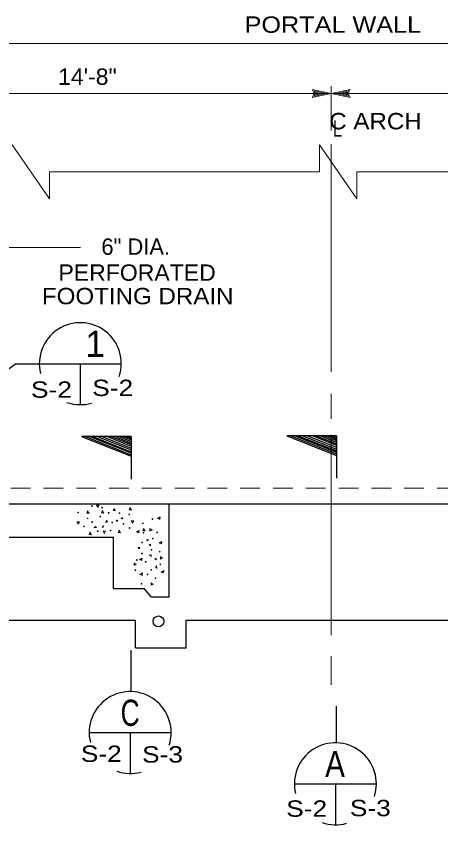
# Model space of a CAD drawing. Extents: x -22.3 to 19.7, y -11.8 to 18.2.
# Drawn here: x -7.13 to -3.89, y 0.19 to 6.36 of the extents above; entities that cross this region are included whole.
import ezdxf
from ezdxf.enums import TextEntityAlignment as Align

# ---------------------------------------------------------------- set-up
doc = ezdxf.new("R2010")
doc.units = 0
doc.header["$LTSCALE"] = 0.05
doc.linetypes.add('MEDIUM_DASHED', pattern=[4.5, 3, -1.5])
doc.layers.add('1', color=7, linetype='Continuous', lineweight=13)
doc.layers.add('2', color=7, linetype='Continuous', lineweight=13)

msp = doc.modelspace()

# ---------------------------------------------------------------- linework, layer by layer
at = {"layer": '1'}
for p, q in [((-8.42042, 6.14831), (-1.02142, 6.14831)), ((-4.72742, 5.76631), (-4.87142, 5.79731)), ((-4.72742, 5.48331), (-4.72742, 5.82331)), ((-4.72742, 5.76631), (-4.58342, 5.79731)), ((-4.72742, 5.76631), (-4.87142, 5.73531)), ((-4.76442, 5.76631), (-4.85842, 5.78631)), ((-4.84942, 5.76631), (-4.85842, 5.78631)), ((-4.76442, 5.76631), (-4.85842, 5.74631)), ((-4.85842, 5.74631), (-4.84942, 5.76631)), ((-4.80042, 5.76631), (-4.84542, 5.77531)), ((-4.84142, 5.76631), (-4.84542, 5.77531)), ((-4.80042, 5.76631), (-4.84542, 5.75631)), ((-4.84542, 5.75631), (-4.84142, 5.76631)), ((-4.72742, 5.76631), (-4.58342, 5.73531)), ((-4.69042, 5.76631), (-4.59642, 5.78631)), ((-4.69042, 5.76631), (-4.59642, 5.74631)), ((-4.65442, 5.76631), (-4.60942, 5.77631)), ((-4.65442, 5.76631), (-4.60942, 5.75731)), ((-4.60942, 5.77631), (-4.61342, 5.76631)), ((-4.61342, 5.76631), (-4.60942, 5.75731)), ((-4.59642, 5.78631), (-4.60542, 5.76631)), ((-4.60542, 5.76631), (-4.59642, 5.74631)), ((-6.87442, 4.96231), (-7.15942, 5.37531)), ((-4.81642, 5.16931), (-4.81642, 5.37531)), ((-4.53142, 4.96231), (-4.81642, 5.37531)), ((-4.72742, 3.64431), (-4.72742, 5.38031)), ((-6.87442, 4.96231), (-6.87442, 5.16931)), ((-6.87442, 5.16931), (-4.81642, 5.16931)), ((-4.53142, 4.96231), (-4.53142, 5.16931)), ((-4.53142, 5.16931), (-2.63142, 5.16931)), ((-4.72742, 3.28631), (-4.72742, 3.47531)), ((-4.72742, 1.63631), (-4.72742, 3.16331)), ((-4.72742, 1.25731), (-4.72742, 1.47531))]:
    msp.add_line(p, q, dxfattribs=at)
at = {"layer": '1', "linetype": 'MEDIUM_DASHED'}
msp.add_line((-8.42042, 2.75631), (-1.02142, 2.75631), dxfattribs=at)
at = {"layer": '1', "lineweight": 25}
for p, q in [((-8.42042, 2.63731), (-1.02142, 2.63731)), ((-5.96342, 1.92531), (-5.96342, 2.63731)), ((-17.08742, 2.38431), (-6.38842, 2.38431)), ((-6.38842, 1.99231), (-6.38842, 2.38431)), ((-6.38842, 1.99231), (-6.15242, 1.99231)), ((-6.09842, 1.92531), (-6.15242, 1.99231)), ((-5.96342, 1.92531), (-6.09842, 1.92531)), ((-8.41542, 1.75131), (-6.21842, 1.75131)), ((-6.21842, 1.53931), (-6.21842, 1.75131)), ((-5.83442, 1.75131), (-3.59642, 1.75131)), ((-5.83442, 1.53931), (-5.83442, 1.75131)), ((-6.21842, 1.53931), (-5.83442, 1.53931))]:
    msp.add_line(p, q, dxfattribs=at)
at = {"layer": '1'}
for points in [[(-4.87142, 5.73531), (-4.85742, 5.76631), (-4.87142, 5.79731)], [(-4.58342, 5.79731), (-4.59742, 5.76631), (-4.58342, 5.73531)], [(-8.42042, 5.76631), (-4.72742, 5.76631), (-1.02142, 5.76631)], [(-8.60842, 3.12131), (-7.23742, 4.59331), (-6.63942, 4.59331)]]:
    msp.add_lwpolyline(points, dxfattribs=at)
at = {"layer": '1', "lineweight": 25}
msp.add_lwpolyline([(-8.34342, 2.81631), (-7.13542, 3.70631), (-6.95242, 3.70631)], dxfattribs=at)
msp.add_circle((-6.04442, 1.74131), 0.0412, dxfattribs=at)
at = {"layer": '2', "lineweight": 25}
for p, q in [((-6.95242, 3.70631), (-6.32842, 3.70631)), ((-6.64042, 3.70631), (-6.64042, 3.39431)), ((-6.60042, 3.15031), (-6.25242, 3.01231)), ((-6.56742, 3.15031), (-6.25242, 3.02531)), ((-6.54442, 3.15031), (-6.25242, 3.03431)), ((-6.50842, 3.15031), (-6.25242, 3.04831)), ((-6.47442, 3.15031), (-6.25242, 3.06231)), ((-6.43342, 3.15031), (-6.25242, 3.07831)), ((-6.40642, 3.15031), (-6.25242, 3.08931)), ((-6.37442, 3.15031), (-6.25242, 3.10131)), ((-6.34542, 3.15031), (-6.25242, 3.11331)), ((-6.31642, 3.15031), (-6.25242, 3.12431)), ((-6.29642, 3.15031), (-6.25242, 3.13231)), ((-6.26942, 3.15031), (-6.25242, 3.14331)), ((-6.25242, 3.15031), (-6.25242, 2.82631)), ((-5.03542, 3.15731), (-4.68742, 3.01931)), ((-5.00242, 3.15731), (-4.68742, 3.03231)), ((-4.97942, 3.15731), (-4.68742, 3.04131)), ((-4.94342, 3.15731), (-4.68742, 3.05531)), ((-4.90942, 3.15731), (-4.68742, 3.06931)), ((-4.86842, 3.15731), (-4.68742, 3.08531)), ((-4.84142, 3.15731), (-4.68742, 3.09631)), ((-4.80942, 3.15731), (-4.68742, 3.10831)), ((-4.78042, 3.15731), (-4.68742, 3.12031)), ((-4.75142, 3.15731), (-4.68742, 3.13131)), ((-4.73142, 3.15731), (-4.68742, 3.13931)), ((-4.70442, 3.15731), (-4.68742, 3.15031)), ((-4.68742, 3.15731), (-4.68742, 2.83331)), ((-6.25242, 1.20731), (-6.25242, 1.52231)), ((-4.68742, 0.81631), (-4.68742, 1.09531)), ((-6.57242, 0.89331), (-5.94842, 0.89331)), ((-6.26042, 0.89331), (-6.26042, 0.58131)), ((-5.00742, 0.50231), (-4.38342, 0.50231)), ((-4.69542, 0.50231), (-4.69542, 0.19031))]:
    msp.add_line(p, q, dxfattribs=at)
at = {"layer": '2'}
for p, q in [((-6.38942, 2.59031), (-6.37942, 2.59931)), ((-6.19142, 2.29431), (-6.20042, 2.30431))]:
    msp.add_line(p, q, dxfattribs=at)
at = {"layer": '2', "lineweight": 25}
for points in [[(-6.25242, 3.15031), (-6.63142, 3.15031), (-6.25242, 3.00031)], [(-4.68742, 3.15731), (-5.06642, 3.15731), (-4.68742, 3.00731)]]:
    msp.add_lwpolyline(points, dxfattribs=at)
at = {"layer": '2'}
for points in [[(-6.50742, 2.61231), (-6.51642, 2.62831), (-6.49742, 2.62831), (-6.50742, 2.61031)], [(-6.37942, 2.60131), (-6.37542, 2.58731), (-6.38942, 2.58731)], [(-6.25942, 2.61031), (-6.26842, 2.59231), (-6.24942, 2.59031), (-6.26342, 2.61031)], [(-6.58242, 2.58531), (-6.59142, 2.56731), (-6.57242, 2.56631), (-6.58742, 2.58531)], [(-6.47042, 2.58731), (-6.47942, 2.56931), (-6.46142, 2.56731), (-6.47442, 2.58731)], [(-6.33042, 2.52831), (-6.32142, 2.53131), (-6.31742, 2.52231), (-6.33042, 2.52631)], [(-6.05142, 2.52831), (-6.03342, 2.51931), (-6.03242, 2.53731), (-6.05142, 2.52331)], [(-6.65842, 2.48531), (-6.66742, 2.50031), (-6.64742, 2.50031), (-6.65842, 2.48231)], [(-6.36642, 2.50431), (-6.36042, 2.51331), (-6.35342, 2.50431), (-6.36442, 2.50431)], [(-6.24442, 2.49331), (-6.25342, 2.50831), (-6.23342, 2.50831), (-6.24442, 2.48931)], [(-6.56442, 2.42231), (-6.57342, 2.40431), (-6.55442, 2.40231), (-6.56942, 2.42231)], [(-6.53442, 2.45831), (-6.52542, 2.46431), (-6.51642, 2.45831), (-6.53842, 2.45531)], [(-6.45842, 2.41331), (-6.46742, 2.42831), (-6.44742, 2.42831), (-6.45842, 2.40931)], [(-6.34242, 2.43731), (-6.35142, 2.41931), (-6.33342, 2.41731), (-6.34642, 2.43731)], [(-6.21142, 2.42431), (-6.19342, 2.41531), (-6.19142, 2.43431), (-6.21142, 2.42031)], [(-6.15542, 2.45031), (-6.16442, 2.43231), (-6.14642, 2.43131), (-6.16042, 2.45031)], [(-6.09442, 2.43931), (-6.10942, 2.43031), (-6.10942, 2.45031), (-6.09042, 2.43931)], [(-6.12942, 2.35331), (-6.13242, 2.36231), (-6.12342, 2.36631), (-6.12742, 2.35331)], [(-6.03842, 2.34131), (-6.02042, 2.33231), (-6.01842, 2.35031), (-6.03842, 2.33731)], [(-6.20242, 2.30431), (-6.18842, 2.30831), (-6.18842, 2.29431)], [(-6.10542, 2.31731), (-6.11442, 2.32331), (-6.10542, 2.33031), (-6.10542, 2.31931)], [(-6.18842, 2.21331), (-6.17042, 2.20431), (-6.16842, 2.22231), (-6.18842, 2.20931)], [(-6.01442, 2.22531), (-6.02942, 2.21631), (-6.02942, 2.23631), (-6.01042, 2.22531)], [(-6.21342, 2.17631), (-6.22942, 2.16731), (-6.22942, 2.18631), (-6.21142, 2.17631)], [(-6.05942, 2.14931), (-6.06542, 2.15831), (-6.05942, 2.16731), (-6.05642, 2.14531)], [(-6.18642, 2.10131), (-6.16842, 2.09231), (-6.16742, 2.11131), (-6.18642, 2.09631)], [(-6.02342, 2.11931), (-6.00542, 2.11031), (-6.00342, 2.12931), (-6.02342, 2.11431)], [(-6.08642, 2.02531), (-6.10142, 2.01631), (-6.10142, 2.03631), (-6.08342, 2.02531)]]:
    msp.add_lwpolyline(points, dxfattribs=at)
for points in [[(-6.47442, 2.45831), (-6.46542, 2.47331), (-6.46142, 2.46231)], [(-6.44742, 2.49631), (-6.43842, 2.51331), (-6.43342, 2.50131)], [(-6.09742, 2.23631), (-6.11442, 2.24531), (-6.10242, 2.25031)], [(-6.05942, 2.20931), (-6.07442, 2.21831), (-6.06342, 2.22231)]]:
    msp.add_lwpolyline(points, close=True, dxfattribs=at)
for centre in [(-6.55147, 2.62014), (-6.47452, 2.60799), (-6.65632, 2.57199), (-6.58477, 2.52654), (-6.48802, 2.54139), (-6.42457, 2.56884), (-6.34132, 2.56704), (-6.26707, 2.55669), (-6.61222, 2.46579), (-6.55012, 2.49909), (-6.39712, 2.49594), (-6.31072, 2.48559), (-6.16222, 2.48874), (-6.08984, 2.52151), (-6.50782, 2.42934), (-6.41062, 2.43384), (-6.26527, 2.45364), (-6.15779, 2.41666), (-6.05474, 2.41846), (-6.16814, 2.34241), (-6.08669, 2.37301), (-6.09704, 2.28661), (-6.16994, 2.25916), (-6.03494, 2.27311), (-6.20909, 2.20921), (-6.14249, 2.19571), (-6.03044, 2.17591), (-6.22124, 2.13226), (-6.12764, 2.09896), (-6.10019, 2.13361), (-6.06689, 2.07151), (-6.17309, 2.02741)]:
    msp.add_circle(centre, 0.00293, dxfattribs=at)
at = {"layer": '2', "lineweight": 25}
for centre, start, end in [((-6.64042, 3.70631), 341.96976, 193.81208), ((-6.64042, 3.70631), 251.04049, 285.74671), ((-6.26042, 0.89331), 341.96976, 193.81208), ((-4.69542, 0.50231), 341.96976, 193.81208), ((-6.26042, 0.89331), 251.04049, 285.74671), ((-4.69542, 0.50231), 251.04049, 285.74671)]:
    msp.add_arc(centre, 0.3125, start, end, dxfattribs=at)

# ---------------------------------------------------------------- texts
at = {"layer": '1'}
for s, width, p in [('PORTAL WALL', 1.15, (-4.71492, 6.22931)), ('14\'-8"', 1.05, (-6.58642, 5.83231)), ('PERFORATED', 1.05, (-6.20742, 4.33831)), ('FOOTING DRAIN', 1.1, (-6.20292, 4.15931))]:
    msp.add_text(s, height=0.125, dxfattribs=dict(at, width=width)).set_placement(p, align=Align.CENTER)
for s, width, p in [('C ARCH', 1.1, (-4.74242, 5.49331)), ('L', 0.75, (-4.71442, 5.43631))]:
    msp.add_text(s, height=0.125, dxfattribs=dict(at, width=width)).set_placement(p)
msp.add_text('6" DIA.', height=0.125, dxfattribs=at).set_placement((-6.21792, 4.53631), align=Align.CENTER)
at = {"layer": '2'}
msp.add_text('1', height=0.2, dxfattribs=at).set_placement((-6.5274, 3.75731), align=Align.CENTER)
for s, height, width, p in [('S-2', 0.125, 1.2, (-6.39342, 3.45931)), ('S-2', 0.125, 1.2, (-6.86042, 3.44631)), ('C', 0.2, 0.75, (-6.26042, 0.94431)), ('S-2', 0.125, 1.2, (-6.48042, 0.66931)), ('S-3', 0.125, 1.2, (-6.01342, 0.66431)), ('A', 0.2, 0.85, (-4.69842, 0.55331)), ('S-2', 0.125, 1.2, (-4.91442, 0.25131)), ('S-3', 0.125, 1.2, (-4.42942, 0.25531))]:
    msp.add_text(s, height=height, dxfattribs=dict(at, width=width)).set_placement(p, align=Align.CENTER)

doc.saveas('drawing.dxf')
